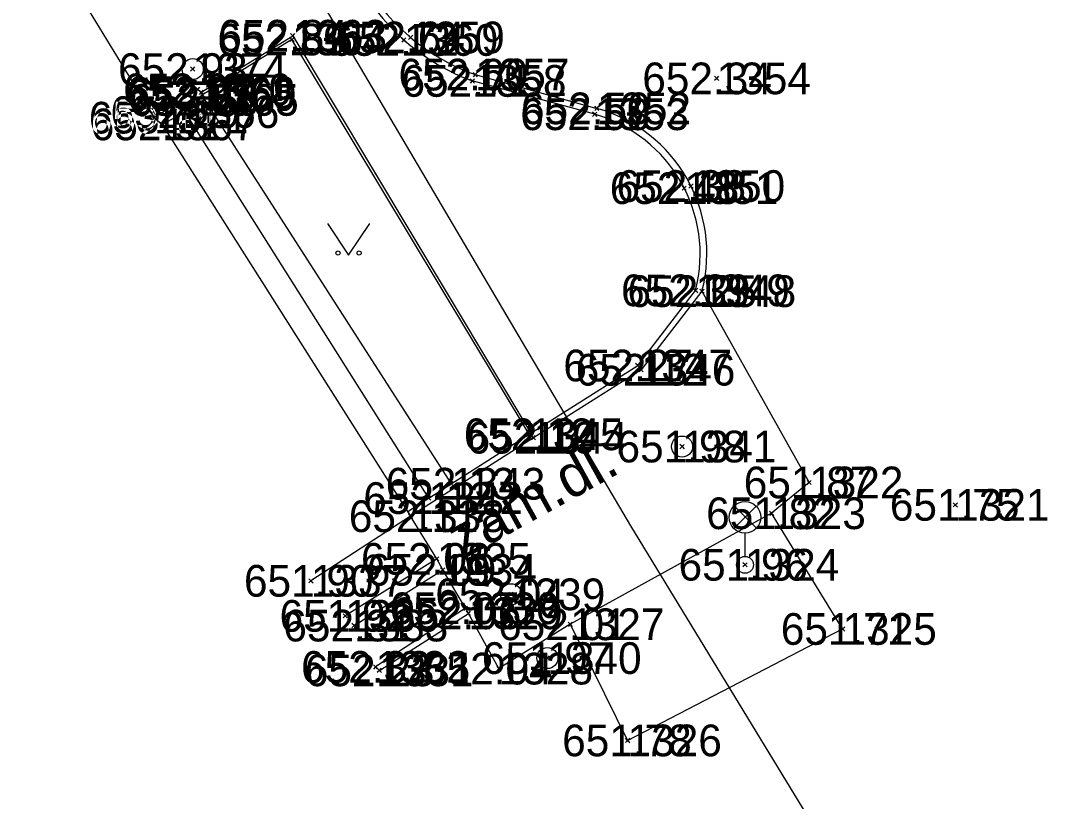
# Model space of a CAD drawing. Extents: x -844765 to -843273, y -997542 to -995529.
# Drawn here: x -844200.5 to -844176.18, y -996740.16 to -996721.66 of the extents above; entities that cross this region are included whole.
import ezdxf

# ---------------------------------------------------------------- set-up
doc = ezdxf.new("R2010")
doc.units = 0
for name, color, linetype in [('Benešův rám', 7, 'Continuous'), ('Betonový strop', 7, 'Continuous'), ('Bod', 7, 'Continuous'), ('Dno', 7, 'Continuous'), ('Groma', 7, 'Continuous'), ('Klenba', 7, 'Continuous'), ('Osa', 7, 'Continuous'), ('Popisy budov', 7, 'Continuous'), ('Sítě podzemní nerozlišené', 7, 'Continuous'), ('Výška', 7, 'Continuous'), ('Číslo bodu', 7, 'Continuous'), ('Řezy', 7, 'Continuous')]:
    doc.layers.add(name, color=color, linetype=linetype)

msp = doc.modelspace()

# ---------------------------------------------------------------- linework, layer by layer
at = {"layer": 'Benešův rám'}
msp.add_lwpolyline([(-844197.33, -996723.96), (-844196.3, -996723.29), (-844196.22, -996723.36), (-844196.19, -996723.42), (-844196.14, -996723.54), (-844196.6, -996723.83), (-844197.14, -996724.12)], dxfattribs=at)
at = {"layer": 'Betonový strop'}
for p, q in [((-844196.14, -996723.54), (-844190.3, -996732.63)), ((-844190.83, -996732.97), (-844196.6, -996723.83)), ((-844190.83, -996732.97), (-844191.327, -996733.294)), ((-844190.64, -996734.41), (-844192.81, -996735.76)), ((-844192.6, -996735.99), (-844190.5, -996734.67)), ((-844189.96, -996735.58), (-844192.09, -996736.97)), ((-844192, -996737.05), (-844189.89, -996735.7))]:
    msp.add_line(p, q, dxfattribs=at)
for points in [[(-844196.22, -996723.36), (-844194.05, -996722.02), (-844188.412, -996731.436)], [(-844188.45, -996731.46), (-844194.07, -996722.11), (-844196.19, -996723.42)], [(-844186.9, -996723.88), (-844189.8, -996723.09)], [(-844189.73, -996722.94), (-844186.85, -996723.74)], [(-844184.36, -996728.07), (-844181.82, -996732.6), (-844182.71, -996733.33), (-844187.48, -996735.96), (-844189.17, -996737.01), (-844189.89, -996735.7), (-844189.96, -996735.58), (-844190.5, -996734.67), (-844190.64, -996734.41), (-844191.26, -996733.4)], [(-844184.36, -996728.07), (-844185.8, -996729.93), (-844188.35, -996731.54), (-844191.26, -996733.4)], [(-844190.83, -996732.97), (-844190.3, -996732.63), (-844188.45, -996731.46), (-844185.88, -996729.83), (-844184.51, -996728.05)], [(-844187.48, -996735.96), (-844186.12, -996738.71), (-844181.03, -996736.07), (-844182.71, -996733.33)]]:
    msp.add_lwpolyline(points, dxfattribs=at)
for centre, radius, start, end in [((-844188.017, -996718.275), 5.134, 210.7479, 249.6838), ((-844188.082, -996718.304), 4.92, 210.7529, 250.4269), ((-844187.807, -996727.171), 3.562, 345.3889, 74.4138), ((-844187.857, -996727.198), 3.454, 345.7237, 73.9139)]:
    msp.add_arc(centre, radius, start, end, dxfattribs=at)
at = {"layer": 'Bod'}
for centre in [(-844196.42, -996722.81), (-844184.83, -996731.75), (-844188.88, -996735.25)]:
    msp.add_circle(centre, 0.25, dxfattribs=at)
at = {"layer": 'Dno'}
msp.add_lwpolyline([(-844193.228, -996726.466), (-844192.728, -996727.216), (-844192.228, -996726.466)], dxfattribs=at)
for centre in [(-844192.978, -996727.166), (-844192.478, -996727.166)]:
    msp.add_circle(centre, 0.05, dxfattribs=at)
at = {"layer": 'Groma'}
for p, q in [((-844183.604, -996733.688), (-844183.076, -996733.16)), ((-844183.068, -996733.685), (-844183.596, -996733.156)), ((-844183.34, -996734.35), (-844183.34, -996733.8))]:
    msp.add_line(p, q, dxfattribs=at)
for centre, radius in [((-844183.34, -996733.425), 0.375), ((-844183.34, -996734.55), 0.2)]:
    msp.add_circle(centre, radius, dxfattribs=at)
at = {"layer": 'Klenba'}
for p, q in [((-844198.98, -996721.26), (-844197.33, -996723.96)), ((-844197.33, -996723.96), (-844197.14, -996724.12)), ((-844197.14, -996724.12), (-844191.26, -996733.4)), ((-844191.26, -996733.4), (-844193.62, -996734.93))]:
    msp.add_line(p, q, dxfattribs=at)
at = {"layer": 'Osa'}
msp.add_lwpolyline([(-844176.215, -996749.76), (-844186.045, -996733.625), (-844196.205, -996716.395), (-844205.915, -996698.84), (-844210.47, -996689.973), (-844217.818, -996675.575), (-844220.61, -996670.045), (-844224.052, -996661.968), (-844227.495, -996653.89), (-844232.17, -996644.045), (-844234.41, -996640.505), (-844239.233, -996635.043), (-844244.055, -996629.58), (-844250.52, -996621.94), (-844256.985, -996614.3), (-844264.955, -996604.805)], dxfattribs=at)
at = {"layer": 'Popisy budov'}
msp.add_circle((-844188.02, -996736.76), 0.25, dxfattribs=at)
at = {"layer": 'Sítě podzemní nerozlišené'}
for p, q in [((-844194.07, -996722.11), (-844194.12, -996722.06)), ((-844194.07, -996722.11), (-844194.12, -996722.16)), ((-844194.05, -996722.02), (-844194.1, -996721.97)), ((-844194.05, -996722.02), (-844194.1, -996722.07)), ((-844194.07, -996722.11), (-844194.02, -996722.06)), ((-844194.07, -996722.11), (-844194.02, -996722.16)), ((-844194.05, -996722.02), (-844194, -996721.97)), ((-844194.05, -996722.02), (-844194, -996722.07)), ((-844191.42, -996722.12), (-844191.47, -996722.07)), ((-844191.42, -996722.12), (-844191.47, -996722.17)), ((-844191.42, -996722.12), (-844191.37, -996722.07)), ((-844191.42, -996722.12), (-844191.37, -996722.17)), ((-844191.26, -996722.06), (-844191.31, -996722.01)), ((-844191.26, -996722.06), (-844191.31, -996722.11)), ((-844191.26, -996722.06), (-844191.21, -996722.01)), ((-844191.26, -996722.06), (-844191.21, -996722.11)), ((-844196.42, -996722.81), (-844196.47, -996722.76)), ((-844196.42, -996722.81), (-844196.47, -996722.86)), ((-844196.42, -996722.81), (-844196.37, -996722.76)), ((-844196.42, -996722.81), (-844196.37, -996722.86)), ((-844189.8, -996723.09), (-844189.85, -996723.04)), ((-844189.8, -996723.09), (-844189.85, -996723.14)), ((-844189.8, -996723.09), (-844189.75, -996723.04)), ((-844189.8, -996723.09), (-844189.75, -996723.14)), ((-844189.73, -996722.94), (-844189.78, -996722.89)), ((-844189.73, -996722.94), (-844189.78, -996722.99)), ((-844189.73, -996722.94), (-844189.68, -996722.89)), ((-844189.73, -996722.94), (-844189.68, -996722.99)), ((-844184.01, -996723.03), (-844184.06, -996722.98)), ((-844184.01, -996723.03), (-844184.06, -996723.08)), ((-844184.01, -996723.03), (-844183.96, -996722.98)), ((-844184.01, -996723.03), (-844183.96, -996723.08)), ((-844196.3, -996723.29), (-844196.35, -996723.24)), ((-844196.3, -996723.29), (-844196.35, -996723.34)), ((-844196.3, -996723.29), (-844196.25, -996723.24)), ((-844196.3, -996723.29), (-844196.25, -996723.34)), ((-844196.22, -996723.36), (-844196.27, -996723.31)), ((-844196.22, -996723.36), (-844196.27, -996723.41)), ((-844196.22, -996723.36), (-844196.17, -996723.31)), ((-844196.22, -996723.36), (-844196.17, -996723.41)), ((-844196.19, -996723.42), (-844196.24, -996723.37)), ((-844196.19, -996723.42), (-844196.24, -996723.47)), ((-844196.19, -996723.42), (-844196.14, -996723.37)), ((-844196.19, -996723.42), (-844196.14, -996723.47)), ((-844196.14, -996723.54), (-844196.19, -996723.49)), ((-844196.14, -996723.54), (-844196.19, -996723.59)), ((-844196.14, -996723.54), (-844196.09, -996723.49)), ((-844196.14, -996723.54), (-844196.09, -996723.59)), ((-844196.6, -996723.83), (-844196.65, -996723.78)), ((-844196.6, -996723.83), (-844196.65, -996723.88)), ((-844196.6, -996723.83), (-844196.55, -996723.78)), ((-844196.6, -996723.83), (-844196.55, -996723.88)), ((-844186.9, -996723.88), (-844186.95, -996723.83)), ((-844186.85, -996723.74), (-844186.9, -996723.69)), ((-844186.85, -996723.74), (-844186.9, -996723.79)), ((-844186.9, -996723.88), (-844186.85, -996723.83)), ((-844186.85, -996723.74), (-844186.8, -996723.69)), ((-844186.85, -996723.74), (-844186.8, -996723.79)), ((-844197.33, -996723.96), (-844197.38, -996723.91)), ((-844197.33, -996723.96), (-844197.38, -996724.01)), ((-844197.33, -996723.96), (-844197.28, -996723.91)), ((-844197.33, -996723.96), (-844197.28, -996724.01)), ((-844197.14, -996724.12), (-844197.19, -996724.07)), ((-844197.14, -996724.12), (-844197.09, -996724.07)), ((-844186.9, -996723.88), (-844186.95, -996723.93)), ((-844186.9, -996723.88), (-844186.85, -996723.93)), ((-844197.14, -996724.12), (-844197.19, -996724.17)), ((-844197.14, -996724.12), (-844197.09, -996724.17)), ((-844184.62, -996725.58), (-844184.67, -996725.53)), ((-844184.62, -996725.58), (-844184.57, -996725.53)), ((-844184.78, -996725.63), (-844184.83, -996725.58)), ((-844184.78, -996725.63), (-844184.83, -996725.68)), ((-844184.78, -996725.63), (-844184.73, -996725.58)), ((-844184.78, -996725.63), (-844184.73, -996725.68)), ((-844184.62, -996725.58), (-844184.67, -996725.63)), ((-844184.62, -996725.58), (-844184.57, -996725.63)), ((-844184.51, -996728.05), (-844184.56, -996728)), ((-844184.51, -996728.05), (-844184.56, -996728.1)), ((-844184.51, -996728.05), (-844184.46, -996728)), ((-844184.51, -996728.05), (-844184.46, -996728.1)), ((-844184.36, -996728.07), (-844184.41, -996728.02)), ((-844184.36, -996728.07), (-844184.41, -996728.12)), ((-844184.36, -996728.07), (-844184.31, -996728.02)), ((-844184.36, -996728.07), (-844184.31, -996728.12)), ((-844185.88, -996729.83), (-844185.93, -996729.78)), ((-844185.88, -996729.83), (-844185.93, -996729.88)), ((-844185.88, -996729.83), (-844185.83, -996729.78)), ((-844185.88, -996729.83), (-844185.83, -996729.88)), ((-844185.8, -996729.93), (-844185.85, -996729.88)), ((-844185.8, -996729.93), (-844185.75, -996729.88)), ((-844185.8, -996729.93), (-844185.85, -996729.98)), ((-844185.8, -996729.93), (-844185.75, -996729.98)), ((-844188.45, -996731.46), (-844188.5, -996731.41)), ((-844188.45, -996731.46), (-844188.5, -996731.51)), ((-844188.45, -996731.46), (-844188.4, -996731.41)), ((-844188.45, -996731.46), (-844188.4, -996731.51)), ((-844188.35, -996731.54), (-844188.4, -996731.49)), ((-844188.35, -996731.54), (-844188.4, -996731.59)), ((-844188.35, -996731.54), (-844188.3, -996731.49)), ((-844188.35, -996731.54), (-844188.3, -996731.59)), ((-844184.83, -996731.75), (-844184.88, -996731.7)), ((-844184.83, -996731.75), (-844184.88, -996731.8)), ((-844184.83, -996731.75), (-844184.78, -996731.7)), ((-844184.83, -996731.75), (-844184.78, -996731.8)), ((-844190.3, -996732.63), (-844190.35, -996732.58)), ((-844190.3, -996732.63), (-844190.25, -996732.58)), ((-844181.82, -996732.6), (-844181.87, -996732.55)), ((-844181.82, -996732.6), (-844181.87, -996732.65)), ((-844181.82, -996732.6), (-844181.77, -996732.55)), ((-844181.82, -996732.6), (-844181.77, -996732.65)), ((-844190.3, -996732.63), (-844190.35, -996732.68)), ((-844190.3, -996732.63), (-844190.25, -996732.68)), ((-844190.83, -996732.97), (-844190.88, -996732.92)), ((-844190.83, -996732.97), (-844190.88, -996733.02)), ((-844190.83, -996732.97), (-844190.78, -996732.92)), ((-844190.83, -996732.97), (-844190.78, -996733.02)), ((-844178.36, -996733.13), (-844178.41, -996733.08)), ((-844178.36, -996733.13), (-844178.31, -996733.08)), ((-844182.71, -996733.33), (-844182.76, -996733.28)), ((-844182.71, -996733.33), (-844182.76, -996733.38)), ((-844182.71, -996733.33), (-844182.66, -996733.28)), ((-844182.71, -996733.33), (-844182.66, -996733.38)), ((-844178.36, -996733.13), (-844178.41, -996733.18)), ((-844178.36, -996733.13), (-844178.31, -996733.18)), ((-844191.26, -996733.4), (-844191.31, -996733.35)), ((-844191.26, -996733.4), (-844191.31, -996733.45)), ((-844191.26, -996733.4), (-844191.21, -996733.35)), ((-844191.26, -996733.4), (-844191.21, -996733.45)), ((-844190.64, -996734.41), (-844190.69, -996734.36)), ((-844190.64, -996734.41), (-844190.69, -996734.46)), ((-844190.64, -996734.41), (-844190.59, -996734.36)), ((-844190.64, -996734.41), (-844190.59, -996734.46)), ((-844183.34, -996734.55), (-844183.39, -996734.5)), ((-844183.34, -996734.55), (-844183.29, -996734.5)), ((-844190.5, -996734.67), (-844190.55, -996734.62)), ((-844190.5, -996734.67), (-844190.55, -996734.72)), ((-844190.5, -996734.67), (-844190.45, -996734.62)), ((-844190.5, -996734.67), (-844190.45, -996734.72)), ((-844183.34, -996734.55), (-844183.39, -996734.6)), ((-844183.34, -996734.55), (-844183.29, -996734.6)), ((-844193.62, -996734.93), (-844193.67, -996734.88)), ((-844193.62, -996734.93), (-844193.67, -996734.98)), ((-844193.62, -996734.93), (-844193.57, -996734.88)), ((-844193.62, -996734.93), (-844193.57, -996734.98)), ((-844188.88, -996735.25), (-844188.93, -996735.2)), ((-844188.88, -996735.25), (-844188.93, -996735.3)), ((-844188.88, -996735.25), (-844188.83, -996735.2)), ((-844188.88, -996735.25), (-844188.83, -996735.3)), ((-844192.81, -996735.76), (-844192.86, -996735.71)), ((-844192.81, -996735.76), (-844192.86, -996735.81)), ((-844192.81, -996735.76), (-844192.76, -996735.71)), ((-844192.81, -996735.76), (-844192.76, -996735.81)), ((-844189.96, -996735.58), (-844190.01, -996735.53)), ((-844189.96, -996735.58), (-844190.01, -996735.63)), ((-844189.96, -996735.58), (-844189.91, -996735.53)), ((-844189.96, -996735.58), (-844189.91, -996735.63)), ((-844189.89, -996735.7), (-844189.94, -996735.65)), ((-844189.89, -996735.7), (-844189.94, -996735.75)), ((-844189.89, -996735.7), (-844189.84, -996735.65)), ((-844189.89, -996735.7), (-844189.84, -996735.75)), ((-844192.6, -996735.99), (-844192.65, -996735.94)), ((-844192.6, -996735.99), (-844192.65, -996736.04)), ((-844192.6, -996735.99), (-844192.55, -996735.94)), ((-844192.6, -996735.99), (-844192.55, -996736.04)), ((-844187.48, -996735.96), (-844187.53, -996735.91)), ((-844187.48, -996735.96), (-844187.53, -996736.01)), ((-844187.48, -996735.96), (-844187.43, -996735.91)), ((-844187.48, -996735.96), (-844187.43, -996736.01)), ((-844181.03, -996736.07), (-844181.08, -996736.02)), ((-844181.03, -996736.07), (-844181.08, -996736.12)), ((-844181.03, -996736.07), (-844180.98, -996736.02)), ((-844181.03, -996736.07), (-844180.98, -996736.12)), ((-844188.02, -996736.76), (-844188.07, -996736.71)), ((-844188.02, -996736.76), (-844187.97, -996736.71)), ((-844192.09, -996736.97), (-844192.14, -996736.92)), ((-844192.09, -996736.97), (-844192.14, -996737.02)), ((-844192.09, -996736.97), (-844192.04, -996736.92)), ((-844192.09, -996736.97), (-844192.04, -996737.02)), ((-844189.17, -996737.01), (-844189.22, -996736.96)), ((-844189.17, -996737.01), (-844189.12, -996736.96)), ((-844188.02, -996736.76), (-844188.07, -996736.81)), ((-844188.02, -996736.76), (-844187.97, -996736.81)), ((-844192, -996737.05), (-844192.05, -996737)), ((-844192, -996737.05), (-844192.05, -996737.1)), ((-844192, -996737.05), (-844191.95, -996737)), ((-844192, -996737.05), (-844191.95, -996737.1)), ((-844189.17, -996737.01), (-844189.22, -996737.06)), ((-844189.17, -996737.01), (-844189.12, -996737.06)), ((-844186.12, -996738.71), (-844186.17, -996738.66)), ((-844186.12, -996738.71), (-844186.07, -996738.66)), ((-844186.12, -996738.71), (-844186.17, -996738.76)), ((-844186.12, -996738.71), (-844186.07, -996738.76))]:
    msp.add_line(p, q, dxfattribs=at)

# ---------------------------------------------------------------- texts
at = {"layer": 'Výška'}
msp.add_text('zám.dl.', height=1, rotation=28.8707, dxfattribs=at).set_placement((-844190.038, -996734.438))
at = {"layer": 'Číslo bodu'}
for s, p in [('1363', (-844194.05, -996722.395)), ('1364', (-844194.07, -996722.485)), ('1360', (-844191.42, -996722.495)), ('1359', (-844191.26, -996722.435)), ('1374', (-844196.42, -996723.185)), ('1357', (-844189.73, -996723.315)), ('1358', (-844189.8, -996723.465)), ('1354', (-844184.01, -996723.405)), ('1370', (-844196.3, -996723.665)), ('1368', (-844196.22, -996723.735)), ('1369', (-844196.19, -996723.795)), ('1365', (-844196.14, -996723.915)), ('1352', (-844186.85, -996724.115)), ('1371', (-844197.33, -996724.335)), ('1366', (-844196.6, -996724.205)), ('1353', (-844186.9, -996724.255)), ('1367', (-844197.14, -996724.495)), ('1351', (-844184.78, -996726.005)), ('1350', (-844184.62, -996725.955)), ('1349', (-844184.51, -996728.425)), ('1348', (-844184.36, -996728.445)), ('1347', (-844185.88, -996730.205)), ('1346', (-844185.8, -996730.305)), ('1345', (-844188.45, -996731.835)), ('1344', (-844188.35, -996731.915)), ('1341', (-844184.83, -996732.125)), ('1343', (-844190.3, -996733.005)), ('1322', (-844181.82, -996732.975)), ('1342', (-844190.83, -996733.345)), ('1321', (-844178.36, -996733.505)), ('1338', (-844191.26, -996733.775)), ('1323', (-844182.71, -996733.705)), ('1335', (-844190.64, -996734.785)), ('1334', (-844190.5, -996735.045)), ('1324', (-844183.34, -996734.925)), ('1337', (-844193.62, -996735.305)), ('1339', (-844188.88, -996735.625)), ('1330', (-844189.96, -996735.955)), ('1336', (-844192.81, -996736.135)), ('1329', (-844189.89, -996736.075)), ('1333', (-844192.6, -996736.365)), ('1327', (-844187.48, -996736.335)), ('1325', (-844181.03, -996736.445)), ('1340', (-844188.02, -996737.135)), ('1332', (-844192.09, -996737.345)), ('1331', (-844192, -996737.425)), ('1328', (-844189.17, -996737.385)), ('1326', (-844186.12, -996739.085))]:
    msp.add_text(s, height=0.75, dxfattribs=at).set_placement(p)
at = {"layer": 'Řezy'}
for s, p in [('652.84', (-844195.813, -996722.395)), ('652.89', (-844195.836, -996722.485)), ('652.72', (-844193.183, -996722.495)), ('652.64', (-844193.043, -996722.435)), ('652.93', (-844198.186, -996723.185)), ('652.60', (-844191.546, -996723.315)), ('652.71', (-844191.474, -996723.465)), ('652.34', (-844185.773, -996723.405)), ('652.97', (-844198.066, -996723.665)), ('652.97', (-844197.986, -996723.735)), ('653.05', (-844197.985, -996723.795)), ('652.56', (-844197.923, -996723.915)), ('652.50', (-844188.645, -996724.115)), ('653.14', (-844198.88, -996724.335)), ('652.59', (-844198.366, -996724.205)), ('652.58', (-844188.663, -996724.255)), ('652.61', (-844198.835, -996724.495)), ('652.48', (-844186.543, -996726.005)), ('652.38', (-844186.383, -996725.955)), ('652.39', (-844186.276, -996728.425)), ('652.25', (-844186.123, -996728.445)), ('652.27', (-844187.643, -996730.205)), ('652.12', (-844187.35, -996730.305)), ('652.12', (-844190, -996731.835)), ('652.10', (-844189.933, -996731.915)), ('651.98', (-844186.383, -996732.125)), ('652.13', (-844191.85, -996733.005)), ('651.87', (-844183.37, -996732.975)), ('652.12', (-844192.38, -996733.345)), ('651.75', (-844179.91, -996733.505)), ('652.11', (-844192.722, -996733.775)), ('651.82', (-844184.26, -996733.705)), ('652.08', (-844192.435, -996734.785)), ('652.09', (-844192.298, -996735.045)), ('651.96', (-844184.914, -996734.925)), ('651.90', (-844195.206, -996735.305)), ('652.04', (-844190.675, -996735.625)), ('652.07', (-844191.755, -996735.955)), ('651.92', (-844194.363, -996736.135)), ('652.06', (-844191.706, -996736.075)), ('652.31', (-844194.274, -996736.365)), ('652.01', (-844189.187, -996736.335)), ('651.71', (-844182.492, -996736.445)), ('651.97', (-844189.573, -996737.135)), ('652.32', (-844193.853, -996737.345)), ('652.23', (-844193.763, -996737.425)), ('652.04', (-844190.965, -996737.385)), ('651.78', (-844187.67, -996739.085))]:
    msp.add_text(s, height=0.75, dxfattribs=at).set_placement(p)

doc.saveas('drawing.dxf')
